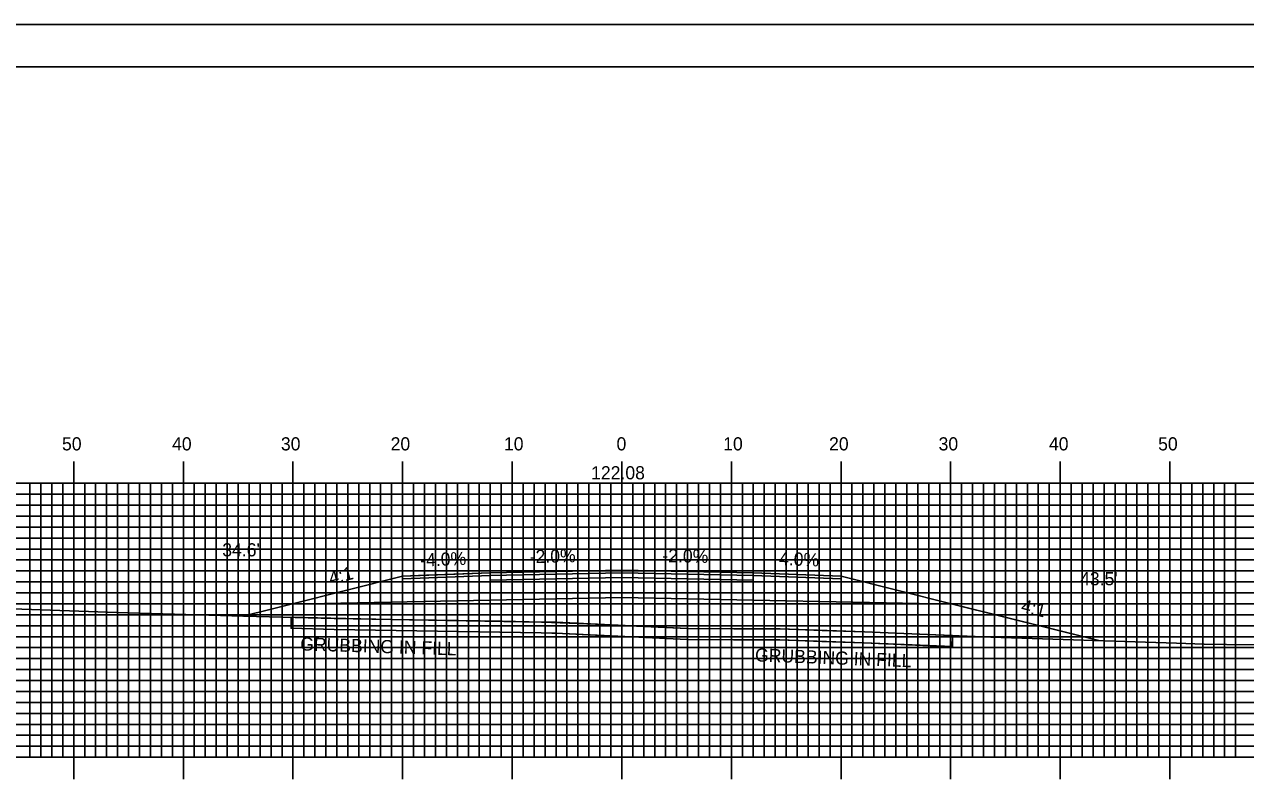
# Model space of a CAD drawing. Extents: x 1771629 to 1771972, y 442591 to 442811.
# Drawn here: x 1771740.1 to 1771851.5, y 442741.2 to 442810.5 of the extents above; entities that cross this region are included whole.
import ezdxf

# ---------------------------------------------------------------- set-up
doc = ezdxf.new("R2010")
doc.units = 0
for name, color, linetype in [('ANNOTATION', 7, 'Continuous'), ('BORDER', 7, 'Continuous'), ('D_Roadway_Centerline', 7, 'Continuous'), ('D_Roadway_Centerline_Text', 7, 'Continuous'), ('D_Roadway_Edge_Shoulder', 7, 'Continuous'), ('D_Roadway_Edge_TW', 7, 'Continuous'), ('D_Roadway_Pavement', 7, 'Continuous'), ('D_Roadway_SlopeLines', 7, 'Continuous'), ('D_Roadway_SubGrade', 7, 'Continuous'), ('D_Text_Standard', 7, 'Continuous'), ('GRUBBING IN FILL', 7, 'Continuous'), ('H_V ANNOTATION', 7, 'Continuous'), ('MAJOR', 7, 'Continuous'), ('MINOR', 7, 'Continuous'), ('PLOT BOUNDARY', 7, 'Continuous'), ('S_Roadway_Centerline', 7, 'Continuous')]:
    doc.layers.add(name, color=color, linetype=linetype)

msp = doc.modelspace()

# ---------------------------------------------------------------- linework, layer by layer
at = {"layer": 'BORDER'}
msp.add_lwpolyline([(1771644.98, 442596.67), (1771964.98, 442596.67), (1771964.98, 442806.67), (1771644.98, 442806.67)], close=True, dxfattribs=at)
at = {"layer": 'D_Roadway_Centerline'}
msp.add_lwpolyline([(1771760.02, 442756.55), (1771760.02, 442756.55), (1771762.58, 442757.19), (1771764.41, 442757.65), (1771764.41, 442757.65), (1771774.57, 442760.19), (1771774.58, 442760.19), (1771776.75, 442760.28), (1771782.58, 442760.51), (1771782.58, 442760.51), (1771794.58, 442760.75), (1771806.58, 442760.51), (1771814.58, 442760.19), (1771824.75, 442757.65), (1771828.45, 442756.72), (1771838.09, 442754.31)], dxfattribs=at)
at = {"layer": 'D_Roadway_Edge_Shoulder'}
for points in [[(1771782.58, 442760.51), (1771774.58, 442760.19), (1771774.58, 442759.94), (1771782.58, 442760.26)], [(1771806.58, 442760.51), (1771814.58, 442760.19), (1771814.58, 442759.94), (1771806.58, 442760.26)]]:
    msp.add_lwpolyline(points, close=True, dxfattribs=at)
at = {"layer": 'D_Roadway_Edge_TW'}
msp.add_lwpolyline([(1771782.58, 442760.26), (1771782.58, 442760.51), (1771794.58, 442760.75), (1771806.58, 442760.51), (1771806.58, 442760.26), (1771794.58, 442760.5)], close=True, dxfattribs=at)
at = {"layer": 'D_Roadway_Pavement'}
msp.add_lwpolyline([(1771782.58, 442759.84), (1771782.58, 442760.26), (1771794.58, 442760.5), (1771806.58, 442760.26), (1771806.58, 442759.84), (1771794.58, 442760.08)], close=True, dxfattribs=at)
at = {"layer": 'D_Roadway_SlopeLines'}
for points in [[(1771774.58, 442760.19), (1771764.41, 442757.65), (1771762.58, 442757.19), (1771760.02, 442756.55)], [(1771814.58, 442760.19), (1771824.75, 442757.65), (1771838.09, 442754.31)]]:
    msp.add_lwpolyline(points, dxfattribs=at)
at = {"layer": 'D_Roadway_SubGrade'}
msp.add_lwpolyline([(1771782.58, 442758.01), (1771764.41, 442757.65), (1771774.58, 442760.19), (1771774.58, 442759.94), (1771782.58, 442760.26), (1771794.58, 442760.5), (1771806.58, 442760.26), (1771814.58, 442759.94), (1771814.58, 442760.19), (1771824.75, 442757.65), (1771806.58, 442758.01), (1771794.58, 442758.25)], close=True, dxfattribs=at)
at = {"layer": 'GRUBBING IN FILL'}
for p, q in [((1771764.41, 442756.44), (1771764.41, 442755.44)), ((1771764.41, 442756.44), (1771764.41, 442755.44)), ((1771824.75, 442754.78), (1771824.75, 442753.78)), ((1771824.75, 442754.78), (1771824.75, 442753.78))]:
    msp.add_line(p, q, dxfattribs=at)
for points in [[(1771764.41, 442756.44), (1771768.03, 442756.35), (1771773.5, 442756.25), (1771777.68, 442756.18), (1771783.67, 442756.08), (1771787.34, 442756.01), (1771792.19, 442755.82), (1771794.58, 442755.7), (1771794.58, 442754.7), (1771789.16, 442754.97), (1771787.23, 442755.01), (1771777.78, 442755.18), (1771768.33, 442755.34), (1771764.41, 442755.44)], [(1771764.41, 442756.44), (1771768.03, 442756.35), (1771773.5, 442756.25), (1771777.68, 442756.18), (1771783.67, 442756.08), (1771787.34, 442756.01), (1771792.19, 442755.82), (1771794.58, 442755.7), (1771794.58, 442754.7), (1771789.16, 442754.97), (1771787.23, 442755.01), (1771777.78, 442755.18), (1771768.33, 442755.34), (1771764.41, 442755.44)], [(1771794.58, 442755.7), (1771800.57, 442755.41), (1771804.8, 442755.39), (1771809.03, 442755.38), (1771812.87, 442755.24), (1771816.71, 442755.11), (1771822.48, 442754.87), (1771824.75, 442754.78), (1771824.71, 442753.75), (1771820.71, 442753.94), (1771816.67, 442754.11), (1771812.84, 442754.24), (1771809.01, 442754.38), (1771804.78, 442754.39), (1771800.55, 442754.41), (1771794.85, 442754.69), (1771794.58, 442754.7)], [(1771794.58, 442755.7), (1771800.57, 442755.41), (1771804.8, 442755.39), (1771809.03, 442755.38), (1771812.87, 442755.24), (1771816.71, 442755.11), (1771822.48, 442754.87), (1771824.75, 442754.78), (1771824.71, 442753.75), (1771820.71, 442753.94), (1771816.67, 442754.11), (1771812.84, 442754.24), (1771809.01, 442754.38), (1771804.78, 442754.39), (1771800.55, 442754.41), (1771794.85, 442754.69), (1771794.58, 442754.7)]]:
    msp.add_lwpolyline(points, close=True, dxfattribs=at)
msp.add_lwpolyline([(1771764.41, 442755.44), (1771768.33, 442755.34), (1771787.23, 442755.01), (1771788.57, 442754.99), (1771789.16, 442754.97), (1771800.55, 442754.41), (1771809.01, 442754.38), (1771816.67, 442754.11), (1771824.75, 442753.78)], dxfattribs=at)
msp.add_lwpolyline([(1771764.41, 442755.44), (1771768.33, 442755.34), (1771787.23, 442755.01), (1771788.57, 442754.99), (1771789.16, 442754.97), (1771800.55, 442754.41), (1771809.01, 442754.38), (1771816.67, 442754.11), (1771824.75, 442753.78)], dxfattribs=at)
at = {"layer": 'MAJOR'}
for p, q in [((1771744.58, 442770.67), (1771744.58, 442768.67)), ((1771754.58, 442770.67), (1771754.58, 442768.67)), ((1771764.58, 442770.67), (1771764.58, 442768.67)), ((1771774.58, 442770.67), (1771774.58, 442768.67)), ((1771784.58, 442770.67), (1771784.58, 442768.67)), ((1771794.58, 442770.67), (1771794.58, 442768.67)), ((1771804.58, 442770.67), (1771804.58, 442768.67)), ((1771814.58, 442770.67), (1771814.58, 442768.67)), ((1771824.58, 442770.67), (1771824.58, 442768.67)), ((1771834.58, 442770.67), (1771834.58, 442768.67)), ((1771844.58, 442770.67), (1771844.58, 442768.67)), ((1771654.58, 442768.67), (1771934.58, 442768.67)), ((1771654.58, 442768.67), (1771934.58, 442768.67)), ((1771744.58, 442743.67), (1771744.58, 442768.67)), ((1771754.58, 442743.67), (1771754.58, 442768.67)), ((1771764.58, 442743.67), (1771764.58, 442768.67)), ((1771774.58, 442743.67), (1771774.58, 442768.67)), ((1771784.58, 442743.67), (1771784.58, 442768.67)), ((1771794.58, 442743.67), (1771794.58, 442768.67)), ((1771804.58, 442743.67), (1771804.58, 442768.67)), ((1771814.58, 442743.67), (1771814.58, 442768.67)), ((1771824.58, 442743.67), (1771824.58, 442768.67)), ((1771834.58, 442743.67), (1771834.58, 442768.67)), ((1771844.58, 442743.67), (1771844.58, 442768.67)), ((1771654.58, 442763.67), (1771934.58, 442763.67)), ((1771654.58, 442758.67), (1771934.58, 442758.67)), ((1771654.58, 442753.67), (1771934.58, 442753.67)), ((1771654.58, 442748.67), (1771934.58, 442748.67)), ((1771654.58, 442743.67), (1771934.58, 442743.67)), ((1771654.58, 442743.67), (1771934.58, 442743.67)), ((1771744.58, 442741.66), (1771744.58, 442743.67)), ((1771754.58, 442741.66), (1771754.58, 442743.67)), ((1771764.58, 442741.66), (1771764.58, 442743.67)), ((1771774.58, 442741.66), (1771774.58, 442743.67)), ((1771784.58, 442741.66), (1771784.58, 442743.67)), ((1771794.58, 442741.66), (1771794.58, 442743.67)), ((1771804.58, 442741.66), (1771804.58, 442743.67)), ((1771814.58, 442741.66), (1771814.58, 442743.67)), ((1771824.58, 442741.66), (1771824.58, 442743.67)), ((1771834.58, 442741.66), (1771834.58, 442743.67)), ((1771844.58, 442741.66), (1771844.58, 442743.67))]:
    msp.add_line(p, q, dxfattribs=at)
at = {"layer": 'MINOR'}
for p, q in [((1771740.58, 442743.67), (1771740.58, 442768.67)), ((1771741.58, 442743.67), (1771741.58, 442768.67)), ((1771742.58, 442743.67), (1771742.58, 442768.67)), ((1771743.58, 442743.67), (1771743.58, 442768.67)), ((1771745.58, 442743.67), (1771745.58, 442768.67)), ((1771746.58, 442743.67), (1771746.58, 442768.67)), ((1771747.58, 442743.67), (1771747.58, 442768.67)), ((1771748.58, 442743.67), (1771748.58, 442768.67)), ((1771749.58, 442743.67), (1771749.58, 442768.67)), ((1771750.58, 442743.67), (1771750.58, 442768.67)), ((1771751.58, 442743.67), (1771751.58, 442768.67)), ((1771752.58, 442743.67), (1771752.58, 442768.67)), ((1771753.58, 442743.67), (1771753.58, 442768.67)), ((1771755.58, 442743.67), (1771755.58, 442768.67)), ((1771756.58, 442743.67), (1771756.58, 442768.67)), ((1771757.58, 442743.67), (1771757.58, 442768.67)), ((1771758.58, 442743.67), (1771758.58, 442768.67)), ((1771759.58, 442743.67), (1771759.58, 442768.67)), ((1771760.58, 442743.67), (1771760.58, 442768.67)), ((1771761.58, 442743.67), (1771761.58, 442768.67)), ((1771762.58, 442743.67), (1771762.58, 442768.67)), ((1771763.58, 442743.67), (1771763.58, 442768.67)), ((1771765.58, 442743.67), (1771765.58, 442768.67)), ((1771766.58, 442743.67), (1771766.58, 442768.67)), ((1771767.58, 442743.67), (1771767.58, 442768.67)), ((1771768.58, 442743.67), (1771768.58, 442768.67)), ((1771769.58, 442743.67), (1771769.58, 442768.67)), ((1771770.58, 442743.67), (1771770.58, 442768.67)), ((1771771.58, 442743.67), (1771771.58, 442768.67)), ((1771772.58, 442743.67), (1771772.58, 442768.67)), ((1771773.58, 442743.67), (1771773.58, 442768.67)), ((1771775.58, 442743.67), (1771775.58, 442768.67)), ((1771776.58, 442743.67), (1771776.58, 442768.67)), ((1771777.58, 442743.67), (1771777.58, 442768.67)), ((1771778.58, 442743.67), (1771778.58, 442768.67)), ((1771779.58, 442743.67), (1771779.58, 442768.67)), ((1771780.58, 442743.67), (1771780.58, 442768.67)), ((1771781.58, 442743.67), (1771781.58, 442768.67)), ((1771782.58, 442743.67), (1771782.58, 442768.67)), ((1771783.58, 442743.67), (1771783.58, 442768.67)), ((1771785.58, 442743.67), (1771785.58, 442768.67)), ((1771786.58, 442743.67), (1771786.58, 442768.67)), ((1771787.58, 442743.67), (1771787.58, 442768.67)), ((1771788.58, 442743.67), (1771788.58, 442768.67)), ((1771789.58, 442743.67), (1771789.58, 442768.67)), ((1771790.58, 442743.67), (1771790.58, 442768.67)), ((1771791.58, 442743.67), (1771791.58, 442768.67)), ((1771792.58, 442743.67), (1771792.58, 442768.67)), ((1771793.58, 442743.67), (1771793.58, 442768.67)), ((1771795.58, 442743.67), (1771795.58, 442768.67)), ((1771796.58, 442743.67), (1771796.58, 442768.67)), ((1771797.58, 442743.67), (1771797.58, 442768.67)), ((1771798.58, 442743.67), (1771798.58, 442768.67)), ((1771799.58, 442743.67), (1771799.58, 442768.67)), ((1771800.58, 442743.67), (1771800.58, 442768.67)), ((1771801.58, 442743.67), (1771801.58, 442768.67)), ((1771802.58, 442743.67), (1771802.58, 442768.67)), ((1771803.58, 442743.67), (1771803.58, 442768.67)), ((1771805.58, 442743.67), (1771805.58, 442768.67)), ((1771806.58, 442743.67), (1771806.58, 442768.67)), ((1771807.58, 442743.67), (1771807.58, 442768.67)), ((1771808.58, 442743.67), (1771808.58, 442768.67)), ((1771809.58, 442743.67), (1771809.58, 442768.67)), ((1771810.58, 442743.67), (1771810.58, 442768.67)), ((1771811.58, 442743.67), (1771811.58, 442768.67)), ((1771812.58, 442743.67), (1771812.58, 442768.67)), ((1771813.58, 442743.67), (1771813.58, 442768.67)), ((1771815.58, 442743.67), (1771815.58, 442768.67)), ((1771816.58, 442743.67), (1771816.58, 442768.67)), ((1771817.58, 442743.67), (1771817.58, 442768.67)), ((1771818.58, 442743.67), (1771818.58, 442768.67)), ((1771819.58, 442743.67), (1771819.58, 442768.67)), ((1771820.58, 442743.67), (1771820.58, 442768.67)), ((1771821.58, 442743.67), (1771821.58, 442768.67)), ((1771822.58, 442743.67), (1771822.58, 442768.67)), ((1771823.58, 442743.67), (1771823.58, 442768.67)), ((1771825.58, 442743.67), (1771825.58, 442768.67)), ((1771826.58, 442743.67), (1771826.58, 442768.67)), ((1771827.58, 442743.67), (1771827.58, 442768.67)), ((1771828.58, 442743.67), (1771828.58, 442768.67)), ((1771829.58, 442743.67), (1771829.58, 442768.67)), ((1771830.58, 442743.67), (1771830.58, 442768.67)), ((1771831.58, 442743.67), (1771831.58, 442768.67)), ((1771832.58, 442743.67), (1771832.58, 442768.67)), ((1771833.58, 442743.67), (1771833.58, 442768.67)), ((1771835.58, 442743.67), (1771835.58, 442768.67)), ((1771836.58, 442743.67), (1771836.58, 442768.67)), ((1771837.58, 442743.67), (1771837.58, 442768.67)), ((1771838.58, 442743.67), (1771838.58, 442768.67)), ((1771839.58, 442743.67), (1771839.58, 442768.67)), ((1771840.58, 442743.67), (1771840.58, 442768.67)), ((1771841.58, 442743.67), (1771841.58, 442768.67)), ((1771842.58, 442743.67), (1771842.58, 442768.67)), ((1771843.58, 442743.67), (1771843.58, 442768.67)), ((1771845.58, 442743.67), (1771845.58, 442768.67)), ((1771846.58, 442743.67), (1771846.58, 442768.67)), ((1771847.58, 442743.67), (1771847.58, 442768.67)), ((1771848.58, 442743.67), (1771848.58, 442768.67)), ((1771849.58, 442743.67), (1771849.58, 442768.67)), ((1771850.58, 442743.67), (1771850.58, 442768.67)), ((1771654.58, 442767.67), (1771934.58, 442767.67)), ((1771654.58, 442766.67), (1771934.58, 442766.67)), ((1771654.58, 442765.67), (1771934.58, 442765.67)), ((1771654.58, 442764.67), (1771934.58, 442764.67)), ((1771654.58, 442762.67), (1771934.58, 442762.67)), ((1771654.58, 442761.67), (1771934.58, 442761.67)), ((1771654.58, 442760.67), (1771934.58, 442760.67)), ((1771654.58, 442759.67), (1771934.58, 442759.67)), ((1771654.58, 442757.67), (1771934.58, 442757.67)), ((1771654.58, 442756.67), (1771934.58, 442756.67)), ((1771654.58, 442755.67), (1771934.58, 442755.67)), ((1771654.58, 442754.67), (1771934.58, 442754.67)), ((1771654.58, 442752.67), (1771934.58, 442752.67)), ((1771654.58, 442751.67), (1771934.58, 442751.67)), ((1771654.58, 442750.67), (1771934.58, 442750.67)), ((1771654.58, 442749.67), (1771934.58, 442749.67)), ((1771654.58, 442747.67), (1771934.58, 442747.67)), ((1771654.58, 442746.67), (1771934.58, 442746.67)), ((1771654.58, 442745.67), (1771934.58, 442745.67)), ((1771654.58, 442744.67), (1771934.58, 442744.67))]:
    msp.add_line(p, q, dxfattribs=at)
at = {"layer": 'PLOT BOUNDARY'}
msp.add_lwpolyline([(1771628.79, 442590.55), (1771968.79, 442590.55), (1771968.79, 442810.55), (1771628.79, 442810.55)], close=True, dxfattribs=at)
at = {"layer": 'S_Roadway_Centerline'}
msp.add_lwpolyline([(1771735.5, 442757.32), (1771748.52, 442756.87), (1771760.06, 442756.55), (1771768.35, 442756.34), (1771787.25, 442756.01), (1771788.6, 442755.99), (1771789.21, 442755.97), (1771800.57, 442755.41), (1771809.03, 442755.38), (1771816.71, 442755.11), (1771828.26, 442754.64), (1771845.19, 442754.08), (1771847.72, 442754), (1771849.75, 442753.96), (1771858.91, 442753.91)], dxfattribs=at)

# ---------------------------------------------------------------- texts
at = {"layer": 'ANNOTATION'}
for s, rotation, p in [('-4.0%', 2.2905, (1771776.21, 442761.06)), ('-2.0%', 1.1457, (1771786.19, 442761.38)), ('-2.0%', 358.8542, (1771798.27, 442761.48)), ('-4.0%', 357.7094, (1771808.37, 442761.24)), ('4:1', 14.0342, (1771768.02, 442759.41)), ('4:1', 345.9609, (1771830.93, 442756.96))]:
    msp.add_text(s, height=1.2, rotation=rotation, dxfattribs=at).set_placement(p)
at = {"layer": 'D_Roadway_Centerline'}
for s, p in [('C', (1771794.58, 442760.75)), ('L', (1771794.58, 442760.74))]:
    msp.add_text(s, height=0.0146, dxfattribs=at).set_placement(p)
at = {"layer": 'D_Roadway_Centerline_Text'}
msp.add_text('122.08', height=1.2, dxfattribs=at).set_placement((1771791.78, 442769.03))
at = {"layer": 'D_Text_Standard'}
for s, p in [("34.6'", (1771758.13, 442762)), ("43.5'", (1771836.39, 442759.36))]:
    msp.add_text(s, height=1.2, dxfattribs=at).set_placement(p)
at = {"layer": 'GRUBBING IN FILL'}
for rotation, p in [(358.1534, (1771765.23, 442753.42)), (357.8127, (1771806.72, 442752.42))]:
    msp.add_text('GRUBBING IN FILL', height=1.2, rotation=rotation, dxfattribs=at).set_placement(p)
at = {"layer": 'H_V ANNOTATION'}
for s, p in [('50', (1771743.51, 442771.67)), ('40', (1771753.55, 442771.67)), ('30', (1771763.48, 442771.67)), ('20', (1771773.49, 442771.67)), ('10', (1771783.83, 442771.67)), ('0', (1771794.1, 442771.67)), ('10', (1771803.83, 442771.67)), ('20', (1771813.49, 442771.67)), ('30', (1771823.48, 442771.67)), ('40', (1771833.55, 442771.67)), ('50', (1771843.51, 442771.67))]:
    msp.add_text(s, height=1.2, dxfattribs=at).set_placement(p)

doc.saveas('drawing.dxf')
